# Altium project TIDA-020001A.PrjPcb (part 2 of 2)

## Sheet TIDA-020001A_LM74700&LMR14030.SchDoc
size 457 x 279 mm; Date: Not shown in title block; ApprovedBy: Not shown in title block; CheckedBy: Not shown in title block; Author: Not shown in title block; CompanyName: Not shown in title block; Engineer: Not shown in title block; Organization: Not shown in title block; Address1: Not shown in title block; Address2: Not shown in title block; Address3: Not shown in title block; Address4: Not shown in title block; DocumentNumber: 1; Revision: Use project parameter SCH_Rev; SheetNumber: 2; SheetTotal: 3; PageSetup: Record=PageOptions¦CenterHorizontal=True¦CenterVertical=True¦PrintScale=1.00¦XCorrection=1.00¦YCorrection=1.00¦PrintKind=0¦BorderSize=5000000¦LeftOffset=0¦BottomOffset=0¦Orientation=2¦PaperLength=1000¦PaperWidth=1000¦Scale=100¦PaperSource=15¦PrintQuality=600¦MediaType=1¦DitherType=10¦PaperKind=Letter¦PrintScaleMode=1
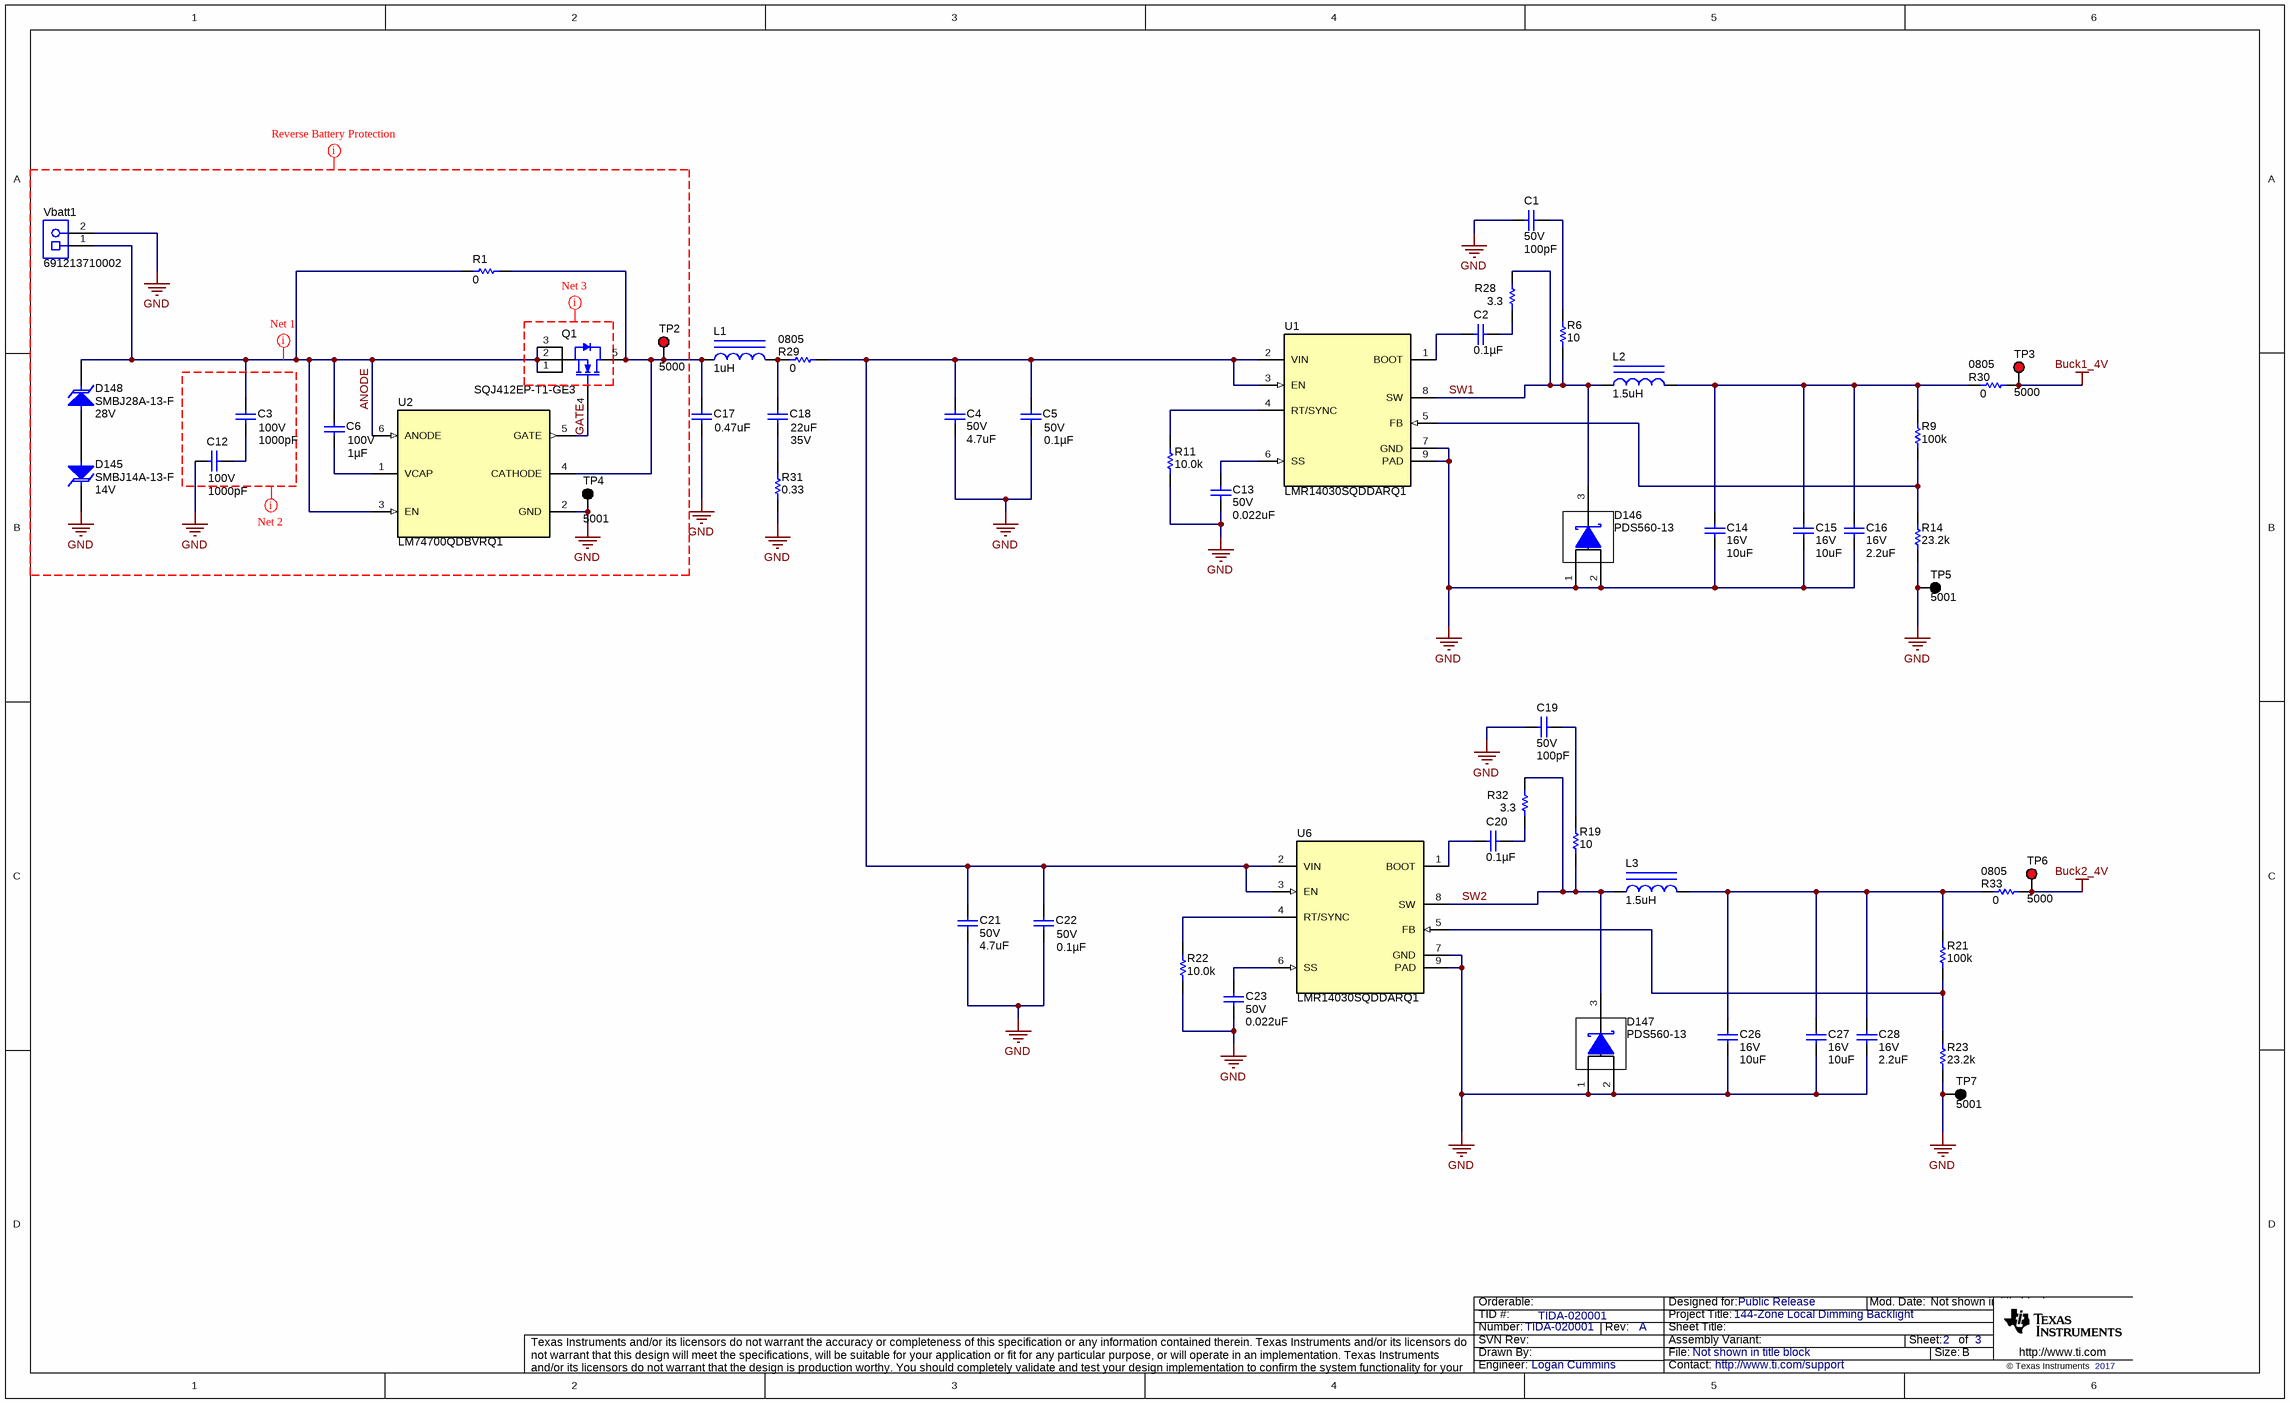
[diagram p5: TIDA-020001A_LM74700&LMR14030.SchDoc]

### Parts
C1  VDC_V: 50V  ValueDisplayed: 100pF  [0402]  (hidden comment: 04025A101FAT2A)
C2  ValueDisplayed: 0.1µF  [0603]  (hidden comment: GRM188R71C104KA01D)
C3  ValueDisplayed: 1000pF  Value2: 100V  [0805_HV]  (hidden comment: 08051A102JAT2A)
C4  VDC_V: 50V  ValueDisplayed: 4.7uF  [1206_180]  (hidden comment: C3216X7R1H475K160AC)
C5  ValueDisplayed: 0.1µF  Value2: 50V  [0805_HV]  (hidden comment: C2012X5R1H104M085AA)
C6  ValueDisplayed: 1µF  Value2: 100V  [1206_180]  (hidden comment: C3216X7R2A105K160AA)
C12  ValueDisplayed: 1000pF  Value2: 100V  [0805_HV]  (hidden comment: 08051A102JAT2A)
C13  VDC_V: 50V  ValueDisplayed: 0.022uF  [0603]  (hidden comment: C0603C223K5RACTU)
C14  VDC_V: 16V  ValueDisplayed: 10uF  [0805_HV]  (hidden comment: CL21B106KOQNNNE)
C15  VDC_V: 16V  ValueDisplayed: 10uF  [0805_HV]  (hidden comment: CL21B106KOQNNNE)
C16  VDC_V: 16V  ValueDisplayed: 2.2uF  [0805_HV]  (hidden comment: C0805C225K4RACTU)
C17  value 0.47uF  [0805_HV]  (hidden comment: C2012X5R1H474K125AB)
C18  ValueDisplayed: 22uF  VDC_V: 35V  [1206_180]  (hidden comment: C3216X5R1V226M160AC)
C19  VDC_V: 50V  ValueDisplayed: 100pF  [0402]  (hidden comment: 04025A101FAT2A)
C20  ValueDisplayed: 0.1µF  [0603]  (hidden comment: GRM188R71C104KA01D)
C21  VDC_V: 50V  ValueDisplayed: 4.7uF  [1206_180]  (hidden comment: C3216X7R1H475K160AC)
C22  ValueDisplayed: 0.1µF  Value2: 50V  [0805_HV]  (hidden comment: C2012X5R1H104M085AA)
C23  VDC_V: 50V  ValueDisplayed: 0.022uF  [0603]  (hidden comment: C0603C223K5RACTU)
C26  VDC_V: 16V  ValueDisplayed: 10uF  [0805_HV]  (hidden comment: CL21B106KOQNNNE)
C27  VDC_V: 16V  ValueDisplayed: 10uF  [0805_HV]  (hidden comment: CL21B106KOQNNNE)
C28  VDC_V: 16V  ValueDisplayed: 2.2uF  [0805_HV]  (hidden comment: C0805C225K4RACTU)
D145  SMBJ14A-13-F  value 14V  [SMB]
D146  PDS560-13  [POWERDI5]
D147  PDS560-13  [POWERDI5]
D148  SMBJ28A-13-F  value 28V  [SMB]
L1  ValueDisplayed: 1uH  [XEL4030_310]  (hidden comment: XEL4030-102MEB)
L2  ValueDisplayed: 1.5uH  [XEL4030_320]  (hidden comment: XEL4030-152MEB)
L3  ValueDisplayed: 1.5uH  [XEL4030_320]  (hidden comment: XEL4030-152MEB)
Q1  SQJ412EP-T1-GE3  [PowerPAK_SO-8L]
R1  ValueDisplayed: 0  [0603]  (hidden comment: CRCW06030000Z0EA)
R6  ValueDisplayed: 10  [0402]  (hidden comment: CRCW040210R0JNED)
R9  ValueDisplayed: 100k  [0603]  (hidden comment: CRCW0603100KFKEA)
R11  ValueDisplayed: 10.0k  [0603]  (hidden comment: CRCW060310K0FKEA)
R14  ValueDisplayed: 23.2k  [0603]  (hidden comment: RC0603FR-0723K2L)
R19  ValueDisplayed: 10  [0402]  (hidden comment: CRCW040210R0JNED)
R21  ValueDisplayed: 100k  [0603]  (hidden comment: CRCW0603100KFKEA)
R22  ValueDisplayed: 10.0k  [0603]  (hidden comment: CRCW060310K0FKEA)
R23  ValueDisplayed: 23.2k  [0603]  (hidden comment: RC0603FR-0723K2L)
R28  ValueDisplayed: 3.3  [0402]  (hidden comment: CRCW04023R30JNED)
R29  PackageReference: 0805  ValueDisplayed: 0  [0805_HV]  (hidden comment: CRCW08050000Z0EA)
R30  PackageReference: 0805  ValueDisplayed: 0  [0805_HV]  (hidden comment: CRCW08050000Z0EA)
R31  ValueDisplayed: 0.33  [0603]  (hidden comment: ERJ-3RQFR33V)
R32  ValueDisplayed: 3.3  [0402]  (hidden comment: CRCW04023R30JNED)
R33  PackageReference: 0805  ValueDisplayed: 0  [0805_HV]  (hidden comment: CRCW08050000Z0EA)
TP2  5000  [Keystone5000]
TP3  5000  [Keystone5000]
TP4  5001  [Keystone5001]
TP5  5001  [Keystone5001]
TP6  5000  [Keystone5000]
TP7  5001  [Keystone5001]
U1  LMR14030SQDDARQ1  [DDA0008E_L]
U2  LM74700QDBVRQ1  [DBV0006A_N]
U6  LMR14030SQDDARQ1  [DDA0008E_L]
Vbatt1  691213710002  [Wurth_691213710002]

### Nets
Buck1_4V: R30.2 TP3.1
Buck2_4V: R33.2 TP6.1
GND: C1.2 C4.2 C5.1 C12.2 C13.2 C14.2 C15.2 C16.2 C17.2 C19.2 C21.2 C22.1 C23.2 C26.2 C27.2 C28.2 D145.1(K) D146.1(A) D146.2(A) D147.1(A) D147.2(A) R11.1 R14.1 R22.1 R23.1 R31.1 TP4.1 TP5.1 TP7.1 U1.7(GND) U1.9(PAD) U2.2(GND) U6.7(GND) U6.9(PAD) Vbatt1.2
ANODE: C3.1 C6.1 D148.1(K) Q1.1(S) Q1.2(S) Q1.3(S) R1.1 U2.3(EN) U2.6(ANODE) Vbatt1.1
GATE: Q1.4(G) U2.5(GATE)
SW1: D146.3(K) L2.1 R6.1 R28.2 U1.8(SW)
SW2: D147.3(K) L3.1 R19.1 R32.2 U6.8(SW)
NetC1_1: C1.1 R6.2
NetC2_1: C2.1 U1.1(BOOT)
NetC2_2: C2.2 R28.1
NetC3_2: C3.2 C12.1
NetC4_1: C4.1 C5.2 C21.1 C22.2 R29.2 U1.2(VIN) U1.3(EN) U6.2(VIN) U6.3(EN)
NetC6_2: C6.2 U2.1(VCAP)
NetC13_1: C13.1 U1.6(SS)
NetC14_1: C14.1 C15.1 C16.1 L2.2 R9.1 R30.1
NetC17_1: C17.1 L1.1 Q1.5(D) R1.2 TP2.1 U2.4(CATHODE)
NetC18_1: C18.1 L1.2 R29.1
NetC18_2: C18.2 R31.2
NetC19_1: C19.1 R19.2
NetC20_1: C20.1 U6.1(BOOT)
NetC20_2: C20.2 R32.1
NetC23_1: C23.1 U6.6(SS)
NetC26_1: C26.1 C27.1 C28.1 L3.2 R21.1 R33.1
NetD145_2: D145.2(A) D148.2(A)
NetR9_2: R9.2 R14.2 U1.5(FB)
NetR11_2: R11.2 U1.4(RT/SYNC)
NetR21_2: R21.2 R23.2 U6.5(FB)
NetR22_2: R22.2 U6.4(RT/SYNC)

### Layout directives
net class Undefined: (no net found under the mark), ANODE, GATE, GND

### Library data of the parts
C1 C19 = CMP-0006196-2: CAP, CERM, 100 pF, 50 V, +/- 1%, C0G/NP0, 0402; Manufacturer: AVX; TaMin_C: -55°C; Polarized: N; SizeAreaWB_mm2: 3; Value1: Unknown; U/M: EA; Value: 100pF; TaMax_C: 125°C; SizeZ_mm: 0.6; SizeX_mm: 1; SizeY_mm: 0.5; CompType: Capacitor; AEC Category: Q200
C2 C20 = GRM188R71C104KA01D: CAP, CERM, 0.1 µF, 16 V, +/- 10%, X7R, 0603; Manufacturer: MuRata; Polarized: N; CompType: Capacitor; Value: 0.1uF; U/M: EA; Cap_F: 0.0000001; Tolerance_%: 10; Value1: Unknown; VDC_V: 16; Value2: 16V; TaMin_C: -55; TaMax_C: 125; SizeArea_mm2: 1.28; SizeAreaWB_mm2: 4.68; SizeX_mm: 1.6; SizeY_mm: 0.8; SizeZ_mm: 1; AEC Category: Q200
C3 C12 = 08051A102JAT2A: CAP, CERM, 1000 pF, 100 V, +/- 5%, C0G/NP0, 0805; Manufacturer: AVX; Polarized: N; CompType: Capacitor; Value: 1000pF; U/M: EA; Cap_F: 0.000000001; Tolerance_%: 5; ESR_ohm: 0.112; Value1: 0.112 ohm; VDC_V: 100; TaMin_C: -55; TaMax_C: 125; Cap_Case: 0805; SizeArea_mm2: 2.5; SizeAreaWB_mm2: 6.75; SizeX_mm: 2; SizeY_mm: 1.25; SizeZ_mm: 1.45; AEC Category: Q200
C4 = CMP-0008702-2: CAP, CERM, 4.7 uF, 50 V, +/- 10%, X7R, 1206; Manufacturer: TDK; Cap_F: 4.7µF; SizeAreaWB_mm2: 10.92; SizeArea_mm2: 5.12; AEC Qualified: N; AEC Category: Q200; Value: 4.7uF; TaMax_C: 125°C; SizeZ_mm: 1.8; TaMin_C: -55°C; SizeY_mm: 1.6; U/M: EA; CompType: Capacitor; SizeX_mm: 3.2; ESR_ohm: 3.158m; IRMS_A: 4.08379A; Value1: 0.003158 ohm
C5 C22 = C2012X5R1H104M085AA: CAP, CERM, 0.1 µF, 50 V,+/- 20%, X5R, 0805; Manufacturer: TDK; Polarized: N; CompType: Capacitor; Value: 0.1uF; U/M: EA; Cap_F: 0.0000001; Tolerance_%: 20; ESR_ohm: 0.02619; Value1: 0.02619 ohm; VDC_V: 50; IRMS_A: 1.29514; TaMin_C: -55; TaMax_C: 85; Cap_Case: 0805; SizeArea_mm2: 2.5; SizeAreaWB_mm2: 6.75; SizeX_mm: 2; SizeY_mm: 1.25; SizeZ_mm: 1.45; AEC Category: Q200; Green_Lifecycle: NRND; Green_REACh: Passed
C6 = C3216X7R2A105K160AA: CAP, CERM, 1 µF, 100 V, +/- 10%, X7R, 1206; Manufacturer: TDK; Polarized: N; CompType: Capacitor; Value: 1uF; U/M: EA; Cap_F: 0.000001; Tolerance_%: 10; ESR_ohm: 0.004575; Value1: 0.004575 ohm; VDC_V: 100; IRMS_A: 3.39639; TaMin_C: -55; TaMax_C: 125; SizeArea_mm2: 5.12; SizeAreaWB_mm2: 10.92; SizeX_mm: 3.2; SizeY_mm: 1.6; SizeZ_mm: 1.8; AEC Category: Q200
C13 C23 = CMP-0006901-4: CAP, CERM, 0.022 uF, 50 V, +/- 10%, X7R, 0603; Manufacturer: Kemet; TaMin_C: -55°C; Polarized: N; Value1: Unknown; U/M: EA; TaMax_C: 125°C; SizeAreaWB_mm2: 4.68; SizeZ_mm: 1; SizeX_mm: 1.6; SizeY_mm: 0.8; SizeArea_mm2: 1.28; CompType: Capacitor; Cap_F: 22nF; AEC Category: Q200
C14 C15 C26 C27 = CMP-0007995-2: CAP, CERM, 10 uF, 16 V, +/- 10%, X7R, 0805; Manufacturer: Samsung Electro-Mechanics; TaMin_C: -55°C; Polarized: N; SizeAreaWB_mm2: 6.75; Value1: Unknown; U/M: EA; Value: 10uF; TaMax_C: 125°C; SizeZ_mm: 1.45; SizeX_mm: 2; SizeY_mm: 1.25; Cap_Case: 0805; SizeArea_mm2: 2.5; Cap_F: 10µF; AEC Category: Q200
C16 C28 = CMP-0007770-2: CAP, CERM, 2.2 uF, 16 V, +/- 10%, X7R, 0805; Manufacturer: Kemet; TaMin_C: -55°C; Polarized: N; SizeAreaWB_mm2: 6.75; Value1: 0.008 ohm; U/M: EA; Value: 2.2uF; TaMax_C: 125°C; SizeZ_mm: 1.45; SizeX_mm: 2; SizeY_mm: 1.25; Cap_Case: 0805; SizeArea_mm2: 2.5; Cap_F: 2.2µF; AEC Category: Q200; ESR_ohm: 8m; IRMS_A: 15.55A
C17 = CMP-0007839-2: CAP, CERM, 0.47 uF, 50 V, +/- 10%, X5R, 0805; Cap_F: 470nF; SizeAreaWB_mm2: 6.75; SizeArea_mm2: 2.5; AEC Qualified: N; AEC Category: Q200; U/M: EA; SizeX_mm: 2
C18 = CMP-0008667-2: CAP, CERM, 22 uF, 35 V, +/- 20%, X5R, 1206; Manufacturer: TDK; TaMin_C: -55°C; Polarized: N; SizeAreaWB_mm2: 10.92; Value1: 0.002398 ohm; U/M: EA; Value: 22uF; TaMax_C: 85°C; SizeZ_mm: 1.8; SizeX_mm: 3.2; SizeY_mm: 1.6; SizeArea_mm2: 5.12; CompType: Capacitor; Cap_F: 22µF; AEC Category: Q200; ESR_ohm: 2.398m; IRMS_A: 4.68507A
C21 = CMP-0008702-2: CAP, CERM, 4.7 uF, 50 V, +/- 10%, X7R, 1206; Manufacturer: TDK; TaMin_C: -55°C; ESR_ohm: 3.158m; Polarized: N; SizeAreaWB_mm2: 10.92; Value1: 0.003158 ohm; U/M: EA; Value: 4.7uF; TaMax_C: 125°C; SizeZ_mm: 1.8; SizeX_mm: 3.2; SizeY_mm: 1.6; SizeArea_mm2: 5.12; CompType: Capacitor; Cap_F: 4.7µF; IRMS_A: 4.08379A; AEC Category: Q200
D145 = SMBJ14A-13-F: Diode, TVS, Uni, 14 V, 600 W, SMB; Manufacturer: Diodes Inc.; U/M: EA; Power_W: 5; Vr_V: 14; Value1: 5W; SizeAreaWB_mm2: 44.156; SizeArea_mm2: 21.336; SizeX_mm: 5.6; SizeY_mm: 3.81; SizeZ_mm: 2.6; AEC Category: Q101
D146 D147 = CMP-0028523-1: Diode, Schottky, 60 V, 5 A, PowerDI5; Manufacturer: Diodes Inc.; Io_A: 5A; Green_Lifecycle: Active; SizeAreaWB_mm2: 49.56; Vr_V: 60V; Green_REACh: Passed; TJmax_C: 150°C; U/M: EA; Value: 60V; SizeZ_mm: 1.05; SizeX_mm: 6.4; SizeY_mm: 3.9; Vf_V: 6.7dV; Value2: 0.67V; SizeArea_mm2: 24.96; AEC Category: Q101
D148 = SMBJ28A-13-F: Diode, TVS, Uni, 28 V, 600 W, SMB; Manufacturer: Diodes Inc.; U/M: EA; Power_W: 5; Vr_V: 28; Value1: 5W; SizeAreaWB_mm2: 44.156; SizeArea_mm2: 21.336; SizeX_mm: 5.6; SizeY_mm: 3.81; SizeZ_mm: 2.6; AEC Category: Q101
L1 = CMP-0061084-1: Inductor, Shielded, Composite, 1 uH, 9 A, 0.0089 ohm, AEC-Q200 Grade 1, SMD; Manufacturer: Coilcraft; Isat: 9A @ 30% inductance drop; Irms: 10.7A @ 40C rise; SizeAreaWB_mm2: 25; DCR_ohm: 8.9m; Value: 1uH; Imax_A: 9A; SizeZ_mm: 3.1; SizeX_mm: 4; SizeArea_mm2: 16; Ind_H: 1µH; AEC Qualified: Y; AEC Grade: 1; AEC Category: Q200
L2 L3 = CMP-0061086-1: Inductor, Shielded, Composite, 1.5 uH, 8.1 A, 0.0151 ohm, AEC-Q200 Grade 1, SMD; Manufacturer: Coilcraft; Isat: 8.5A @ 30% inductance drop; Irms: 8.1A @ 40C rise; SizeAreaWB_mm2: 25; DCR_ohm: 0.0151; Value: 1.5uH; Imax_A: 8.1A; SizeZ_mm: 3.2; SizeX_mm: 4; SizeArea_mm2: 16; Ind_H: 1.5µH; AEC Qualified: Y; AEC Grade: 1; AEC Category: Q200
Q1 = SQJ412EP-T1-GE3: MOSFET, N-CH, 40 V, 32 A, PowerPAK_SO-8L; Manufacturer: Vishay-Siliconix; Alternate Manufacturer: None; SymbolCreator: a0412235; U/M: EA; ChType: N; Value: 40V; VdsMax_V: 40; Value1: 0.0052 ohm; Rdson45_ohm: 0.0052; Value2: 80 nC; QgTyp_nC: 80; Vgs_V: 20; IdsMax_A: 32; AEC Category: Q101
R1 = CRCW06030000Z0EA: RES, 0, 5%, 0.1 W, 0603; Manufacturer: Vishay-Dale; CompType: Resistor; Value: 0; Value_Code: 0000; Tolerance_%: 5; Power_W: 0.1; Value2: 0.1W; VDC_V: 75; TempCo: 200 ppm/C; SizeArea_mm2: 1.28; SizeX_mm: 1.6; SizeY_mm: 0.8; SizeZ_mm: 1; EIA_Code: E24; U/M: EA; AEC Category: Q200; Green_Lifecycle: Active; Green_REACh: Passed
R6 R19 = CMP-0026827-3: RES, 10, 5%, 0.063 W, AEC-Q200 Grade 0, 0402; Manufacturer: Vishay-Dale; Power_W: 63mW; TempCo: 200 ppm/C; Value_Code: 10R0; Value: 10; EIA_Code: E24; SizeX_mm: 1; SizeY_mm: 0.5; SizeZ_mm: 0.6; Value2: 0.063W; CompType: Resistor; AEC Qualified: Y; VDC_V: 50V; AEC Category: Q200; AEC Grade: 0
R9 R21 = CMP-0021990-4: RES, 100 k, 1%, 0.1 W, AEC-Q200 Grade 0, 0603; Manufacturer: Vishay-Dale; Power_W: 100mW; TempCo: 100 ppm/C; Value: 100k; EIA_Code: E96; SizeX_mm: 1.6; SizeY_mm: 0.8; SizeZ_mm: 1; Value2: 0.1W; SizeArea_mm2: 1.28; AEC Qualified: Y; VDC_V: 75V; AEC Category: Q200; AEC Grade: 0
R11 = CMP-0021998-4: RES, 10.0 k, 1%, 0.1 W, AEC-Q200 Grade 0, 0603; Manufacturer: Vishay-Dale; Power_W: 100mW; TempCo: 100 ppm/C; Value_Code: 10k0; Value: 10.0k; EIA_Code: E96; Res_ohm: 10k; SizeX_mm: 1.6; SizeY_mm: 0.8; SizeZ_mm: 1; Value2: 0.1W; SizeArea_mm2: 1.28; CompType: Resistor; AEC Qualified: Y; VDC_V: 75V; AEC Category: Q200; AEC Grade: 0
R14 R23 = CMP-0022933-5: RES, 23.2 k, 1%, 0.1 W, 0603; Manufacturer: Yageo; Power_W: 100mW; TempCo: 100 ppm/C; Value_Code: 23k2; Value: 23.2k; EIA_Code: E96; SizeX_mm: 1.6; SizeY_mm: 0.8; SizeZ_mm: 1; Value2: 0.1W; SizeArea_mm2: 1.28; AEC Qualified: N; VDC_V: 75V; AEC Category: Q200; SizeAreaWB_mm2: 4.68
R22 = CMP-0021998-4: RES, 10.0 k, 1%, 0.1 W, AEC-Q200 Grade 0, 0603; Manufacturer: Vishay-Dale; Power_W: 100mW; TempCo: 100 ppm/C; Value_Code: 10k0; Value: 10.0k; EIA_Code: E96; Res_ohm: 10k; SizeX_mm: 1.6; SizeY_mm: 0.8; SizeZ_mm: 1; Value2: 0.1W; SizeArea_mm2: 1.28; AEC Qualified: Y; VDC_V: 75V; AEC Category: Q200; AEC Grade: 0
R28 R32 = CMP-0026926-3: RES, 3.3, 5%, 0.063 W, AEC-Q200 Grade 0, 0402; Manufacturer: Vishay-Dale; Power_W: 63mW; TempCo: 200 ppm/C; Value_Code: 3R30; Value: 3.3; EIA_Code: E24; SizeX_mm: 1; SizeY_mm: 0.5; SizeZ_mm: 0.6; Value2: 0.063W; CompType: Resistor; AEC Qualified: Y; VDC_V: 50V; AEC Category: Q200; AEC Grade: 0
R29 R30 R33 = CMP-0020442-3: RES, 0, 5%, 0.125 W, AEC-Q200 Grade 0, 0805; Manufacturer: Vishay-Dale; Power_W: 125mW; TempCo: 200 ppm/C; Value_Code: 0000; Value: 0; EIA_Code: E24; SizeX_mm: 2; SizeY_mm: 1.25; SizeZ_mm: 1.45; Value2: 0.125W; SizeArea_mm2: 2.5; CompType: Resistor; AEC Qualified: Y; VDC_V: 150V; AEC Category: Q200
R31 = ERJ-3RQFR33V: RES, 0.33, 1%, 0.1 W, 0603; Manufacturer: Panasonic; CompType: Resistor; Value: 0.33; Value_Code: R330; Tolerance_%: 1; Power_W: 0.1; Value2: 0.1W; TempCo: 300 ppm/C; SizeArea_mm2: 1.28; SizeX_mm: 1.6; SizeY_mm: 0.8; EIA_Code: E96; U/M: EA; AEC Category: Q200; Green_Lifecycle: Active; Green_REACh: Passed
TP2 TP3 TP6 = CMP-0055137-1: Test Point, Miniature, Red, TH; Manufacturer: Keystone; CNHeader: FALSE; Green_Lifecycle: Active; Green_REACh: Passed; ContactFinish: Silver; CT: TRUE
TP4 TP5 TP7 = CMP-0055138-1: Test Point, Miniature, Black, TH; Manufacturer: Keystone; CNHeader: FALSE; Green_Lifecycle: Active; Green_REACh: Passed; ContactFinish: Silver; CT: TRUE
U1 U6 = CMP-0076368-2: Automotive 40V, 3.5A SIMPLE SWITCHER(R), 2.2MHz Step-Down Regulator with 40uA IQ, DDA0008E (SOIC-8); Manufacturer: Texas Instruments; SizeZ_mm: 1.7; SizeX_mm: 5.0; SizeY_mm: 6.2; SizeArea_mm2: 31.0; CompType: IC; U/M: EA; SizeAreaWB_mm2: 57.4
U2 = CMP-0013281-4: Low Iq Always ON Smart Diode Controller, DBV0006A (SOT-23-6); Alternate PartNumber: LM74700QDBVTQ1; Manufacturer: Texas Instruments; SizeZ_mm: 1.45; SizeX_mm: 2.8; SizeY_mm: 2.9; SizeArea_mm2: 8.12; CompType: IC; SizeAreaWB_mm2: 14.82; AEC Category: Q200; AEC Qualified: Y
Vbatt1 = 691213710002: Terminal Block, 2x1, Brass, TH; Manufacturer: Wurth Elektronik; SymbolCreator: a0412235; Pitch_mm: 5; Gender: Female; Row_Count: 1

## Sheet TIDA-020001A_Hardware.SchDoc
size 431 x 279 mm; Date: Not shown in title block; ApprovedBy: Not shown in title block; CheckedBy: Not shown in title block; Author: Not shown in title block; CompanyName: Not shown in title block; Engineer: Not shown in title block; Organization: Not shown in title block; Address1: Not shown in title block; Address2: Not shown in title block; Address3: Not shown in title block; Address4: Not shown in title block; DocumentNumber: 1; Revision: Use project parameter SCH_Rev; SheetNumber: 3; SheetTotal: 3; PageSetup: Record=PageOptions¦CenterHorizontal=True¦CenterVertical=True¦PrintScale=1.00¦XCorrection=1.00¦YCorrection=1.00¦PrintKind=0¦BorderSize=5000000¦LeftOffset=0¦BottomOffset=0¦Orientation=2¦PaperLength=1000¦PaperWidth=1000¦Scale=100¦PaperSource=15¦PrintQuality=600¦MediaType=1¦DitherType=10¦PaperKind=Letter¦PrintScaleMode=1
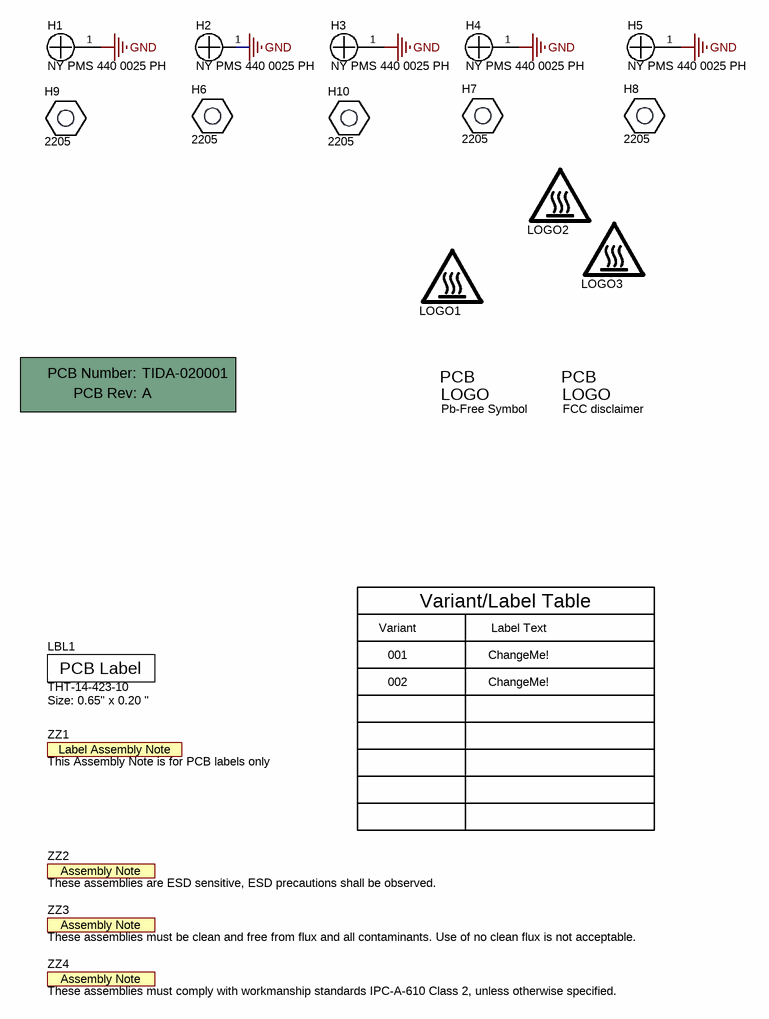
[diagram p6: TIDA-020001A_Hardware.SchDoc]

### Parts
(Parts that share a designator on the sheet are numbered #1, #2 ... from top to bottom, then left to right.)
!PCB  Printed Circuit Board  (value not drawn)  (mechanical)
H1  NY PMS 440 0025 PH  [NY PMS 440 0025 PH]
H2  NY PMS 440 0025 PH  [NY PMS 440 0025 PH]
H3  NY PMS 440 0025 PH  [NY PMS 440 0025 PH]
H4  NY PMS 440 0025 PH  [NY PMS 440 0025 PH]
H5  NY PMS 440 0025 PH  [NY PMS 440 0025 PH]
H6  2205  [KEYSTONE_2205]
H7  2205  [KEYSTONE_2205]
H8  2205  [KEYSTONE_2205]
H9  2205  [KEYSTONE_2205]
H10  2205  [KEYSTONE_2205]
LBL1  THT-14-423-10  Note: Size: 0.65" x 0.20 "  [Label_650x200]
LOGO1  CAUTION HOT SURFACE  [IEC_HotSurface_Small]  (value not drawn)  (no BOM)
LOGO2#1  CAUTION HOT SURFACE  [IEC_HotSurface_Small]  (value not drawn)  (no BOM)
Logo2#2  Pb-Free Symbol  [Pb-Free_Overlay_Small]  (no BOM)
LOGO3#1  CAUTION HOT SURFACE  [IEC_HotSurface_Small]  (value not drawn)  (no BOM)
Logo3#2  FCC disclaimer  [FCC_disclaimer]  (no BOM)
ZZ1  This Assembly Note is for PCB labels only  [AssemblyNoteLabel]  (no BOM)
ZZ2  These assemblies are ESD sensitive, ESD precautions shall be observed.  [AssemblyNote]  (no BOM)
ZZ3  These assemblies must be clean and free from flux and all contaminants. Use of no clean flux is not acceptable.  [AssemblyNote]  (no BOM)
ZZ4  These assemblies must comply with workmanship standards IPC-A-610 Class 2, unless otherwise specified.  [AssemblyNote]  (no BOM)

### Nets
GND: H1.1 H2.1 H3.1 H4.1 H5.1

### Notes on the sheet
- Variant
- Variant/Label Table
- Label Text
- 001
- 002
- ChangeMe!

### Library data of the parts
!PCB = CMP-0003618-2: Manufacturer: Any; PartNumber: TIDA-020001
H1-H5 = NY PMS 440 0025 PH: Machine Screw, Round, #4-40 x 1/4, Nylon, Philips panhead; Manufacturer: B&F Fastener Supply; CompType: Hardware; SymbolCreator: codlsc; U/M: EA
H6-H10 = 2205: Standoff, Hex, 1"L #4-40 Aluminum; Manufacturer: Keystone; SymbolCreator: a0412235
LBL1 = CMP-0003625-1: Thermal Transfer Printable Labels, 0.650" W x 0.200" H - 10,000 per roll; Manufacturer: Brady; CompType: Label
LOGO1 LOGO2#1 LOGO3#1 = IEC_HotSurface: IEC 61010-1 Hot Surface Warning; SymbolCreator: a0412235
Logo2#2 = CMP-0074839-1: SymbolCreator: a0412235; Library Reference: Logo
Logo3#2 = CMP-0074847-1: FCC_disclaimer; Library Reference: Logo
ZZ1 = CMP-0003616-3
ZZ2 = CMP-0077236-1
ZZ3 = CMP-0077237-1
ZZ4 = CMP-0077238-1

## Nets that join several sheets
3V3_LS: TIDA-020001A_TLC6C5724 (14 pins), TIDA-020001A_TLC6C5716 (9 pins), TIDA-020001A_OPT&C2000 (C9.1 R4.2 TP10.1 U4.6)
Buck1_4V: TIDA-020001A_TLC6C5724 (U8.38 U9.38), TIDA-020001A_TLC6C5716 (U14.38), TIDA-020001A_OPT&C2000 (5 pins), TIDA-020001A_LEDs (64 pins), TIDA-020001A_LM74700&LMR14030 (R30.2 TP3.1)
Buck2_4V: TIDA-020001A_TLC6C5724 (U10.38 U11.38), TIDA-020001A_TLC6C5716 (U12.38 U13.38), TIDA-020001A_LEDs (80 pins), TIDA-020001A_LM74700&LMR14030 (R33.2 TP6.1)
GND: TIDA-020001A_TLC6C5724 (24 pins), TIDA-020001A_TLC6C5716 (18 pins), TIDA-020001A_OPT&C2000 (21 pins), TIDA-020001A_LM74700&LMR14030 (35 pins), TIDA-020001A_Hardware (5 pins)
BLANK: TIDA-020001A_TLC6C5724 (U8.36 U9.36 U10.36 U11.36), TIDA-020001A_TLC6C5716 (U12.36 U13.36 U14.36), TIDA-020001A_OPT&C2000 (J1.2)
ERR: TIDA-020001A_TLC6C5724 (6 pins), TIDA-020001A_TLC6C5716 (U12.20 U13.20 U14.20), TIDA-020001A_OPT&C2000 (J2.5)
GCLK: TIDA-020001A_TLC6C5724 (U8.4 U9.4 U10.4 U11.4), TIDA-020001A_TLC6C5716 (U12.4 U13.4 U14.4), TIDA-020001A_OPT&C2000 (R27.1)
LATCH: TIDA-020001A_TLC6C5724 (U8.3 U9.3 U10.3 U11.3), TIDA-020001A_TLC6C5716 (U12.3 U13.3 U14.3), TIDA-020001A_OPT&C2000 (J2.2)
MISO: TIDA-020001A_TLC6C5716 (U14.19), TIDA-020001A_OPT&C2000 (J2.9)
MOSI: TIDA-020001A_TLC6C5724 (U9.1), TIDA-020001A_OPT&C2000 (J1.7)
OUTA0: TIDA-020001A_TLC6C5716 (U12.8), TIDA-020001A_LEDs (D97.1)
OUTA0/1: TIDA-020001A_TLC6C5716 (U13.8), TIDA-020001A_LEDs (D113.1)
OUTA0/3: TIDA-020001A_TLC6C5716 (U14.8), TIDA-020001A_LEDs (D129.1)
OUTA1: TIDA-020001A_TLC6C5716 (R35.2 TP12.1), TIDA-020001A_LEDs (D99.1)
OUTA1/1: TIDA-020001A_TLC6C5716 (U13.11), TIDA-020001A_LEDs (D115.1)
OUTA1/3: TIDA-020001A_TLC6C5716 (U14.11), TIDA-020001A_LEDs (D131.1)
OUTA2: TIDA-020001A_TLC6C5716 (U12.14), TIDA-020001A_LEDs (D101.1)
OUTA2/1: TIDA-020001A_TLC6C5716 (U13.14), TIDA-020001A_LEDs (D117.1)
OUTA2/3: TIDA-020001A_TLC6C5716 (U14.14), TIDA-020001A_LEDs (D133.1)
OUTA3: TIDA-020001A_TLC6C5716 (U12.17), TIDA-020001A_LEDs (D103.1)
OUTA3/1: TIDA-020001A_TLC6C5716 (U13.17), TIDA-020001A_LEDs (D119.1)
OUTA3/3: TIDA-020001A_TLC6C5716 (U14.17), TIDA-020001A_LEDs (D135.1)
OUTA4: TIDA-020001A_TLC6C5716 (U12.22), TIDA-020001A_LEDs (D105.1)
OUTA4/1: TIDA-020001A_TLC6C5716 (U13.22), TIDA-020001A_LEDs (D121.1)
OUTA4/3: TIDA-020001A_TLC6C5716 (U14.22), TIDA-020001A_LEDs (D137.1)
OUTA5: TIDA-020001A_TLC6C5716 (U12.25), TIDA-020001A_LEDs (D107.1)
OUTA5/1: TIDA-020001A_TLC6C5716 (U13.25), TIDA-020001A_LEDs (D123.1)
OUTA5/3: TIDA-020001A_TLC6C5716 (U14.25), TIDA-020001A_LEDs (D139.1)
OUTA6: TIDA-020001A_TLC6C5716 (U12.28), TIDA-020001A_LEDs (D109.1)
OUTA6/1: TIDA-020001A_TLC6C5716 (U13.28), TIDA-020001A_LEDs (D125.1)
OUTA6/3: TIDA-020001A_TLC6C5716 (U14.28), TIDA-020001A_LEDs (D141.1)
OUTA7: TIDA-020001A_TLC6C5716 (U12.31), TIDA-020001A_LEDs (D111.1)
OUTA7/1: TIDA-020001A_TLC6C5716 (U13.31), TIDA-020001A_LEDs (D127.1)
OUTA7/3: TIDA-020001A_TLC6C5716 (U14.31), TIDA-020001A_LEDs (D143.1)
OUTB0: TIDA-020001A_TLC6C5724 (U8.9), TIDA-020001A_LEDs (D3.1)
OUTB0/1: TIDA-020001A_TLC6C5724 (U9.9), TIDA-020001A_LEDs (D27.1)
OUTB0/2: TIDA-020001A_TLC6C5724 (U10.9), TIDA-020001A_LEDs (D51.1)
OUTB0/3: TIDA-020001A_TLC6C5724 (U11.9), TIDA-020001A_LEDs (D75.1)
OUTB0/4: TIDA-020001A_TLC6C5716 (R34.2 TP1.1), TIDA-020001A_LEDs (D98.1)
OUTB0/5: TIDA-020001A_TLC6C5716 (U13.9), TIDA-020001A_LEDs (D114.1)
OUTB0/7: TIDA-020001A_TLC6C5716 (U14.9), TIDA-020001A_LEDs (D130.1)
OUTB1: TIDA-020001A_TLC6C5724 (U8.12), TIDA-020001A_LEDs (D6.1)
OUTB1/1: TIDA-020001A_TLC6C5724 (U9.12), TIDA-020001A_LEDs (D30.1)
OUTB1/2: TIDA-020001A_TLC6C5724 (U10.12), TIDA-020001A_LEDs (D54.1)
OUTB1/3: TIDA-020001A_TLC6C5724 (U11.12), TIDA-020001A_LEDs (D78.1)
OUTB1/4: TIDA-020001A_TLC6C5716 (U12.12), TIDA-020001A_LEDs (D100.1)
OUTB1/5: TIDA-020001A_TLC6C5716 (U13.12), TIDA-020001A_LEDs (D116.1)
OUTB1/7: TIDA-020001A_TLC6C5716 (U14.12), TIDA-020001A_LEDs (D132.1)
OUTB2: TIDA-020001A_TLC6C5724 (U8.15), TIDA-020001A_LEDs (D9.1)
OUTB2/1: TIDA-020001A_TLC6C5724 (U9.15), TIDA-020001A_LEDs (D33.1)
OUTB2/2: TIDA-020001A_TLC6C5724 (U10.15), TIDA-020001A_LEDs (D57.1)
OUTB2/3: TIDA-020001A_TLC6C5724 (U11.15), TIDA-020001A_LEDs (D81.1)
OUTB2/4: TIDA-020001A_TLC6C5716 (U12.15), TIDA-020001A_LEDs (D102.1)
OUTB2/5: TIDA-020001A_TLC6C5716 (U13.15), TIDA-020001A_LEDs (D118.1)
OUTB2/7: TIDA-020001A_TLC6C5716 (U14.15), TIDA-020001A_LEDs (D134.1)
OUTB3: TIDA-020001A_TLC6C5724 (U8.18), TIDA-020001A_LEDs (D12.1)
OUTB3/1: TIDA-020001A_TLC6C5724 (U9.18), TIDA-020001A_LEDs (D36.1)
OUTB3/2: TIDA-020001A_TLC6C5724 (U10.18), TIDA-020001A_LEDs (D60.1)
OUTB3/3: TIDA-020001A_TLC6C5724 (U11.18), TIDA-020001A_LEDs (D84.1)
OUTB3/4: TIDA-020001A_TLC6C5716 (U12.18), TIDA-020001A_LEDs (D104.1)
OUTB3/5: TIDA-020001A_TLC6C5716 (U13.18), TIDA-020001A_LEDs (D120.1)
OUTB3/7: TIDA-020001A_TLC6C5716 (U14.18), TIDA-020001A_LEDs (D136.1)
OUTB4: TIDA-020001A_TLC6C5724 (U8.21), TIDA-020001A_LEDs (D15.1)
OUTB4/1: TIDA-020001A_TLC6C5724 (U9.21), TIDA-020001A_LEDs (D39.1)
OUTB4/2: TIDA-020001A_TLC6C5724 (U10.21), TIDA-020001A_LEDs (D63.1)
OUTB4/3: TIDA-020001A_TLC6C5724 (U11.21), TIDA-020001A_LEDs (D87.1)
OUTB4/4: TIDA-020001A_TLC6C5716 (U12.21), TIDA-020001A_LEDs (D106.1)
OUTB4/5: TIDA-020001A_TLC6C5716 (U13.21), TIDA-020001A_LEDs (D122.1)
OUTB4/7: TIDA-020001A_TLC6C5716 (U14.21), TIDA-020001A_LEDs (D138.1)
OUTB5: TIDA-020001A_TLC6C5724 (U8.24), TIDA-020001A_LEDs (D18.1)
OUTB5/1: TIDA-020001A_TLC6C5724 (U9.24), TIDA-020001A_LEDs (D42.1)
OUTB5/2: TIDA-020001A_TLC6C5724 (U10.24), TIDA-020001A_LEDs (D66.1)
OUTB5/3: TIDA-020001A_TLC6C5724 (U11.24), TIDA-020001A_LEDs (D90.1)
OUTB5/4: TIDA-020001A_TLC6C5716 (U12.24), TIDA-020001A_LEDs (D108.1)
OUTB5/5: TIDA-020001A_TLC6C5716 (U13.24), TIDA-020001A_LEDs (D124.1)
OUTB5/7: TIDA-020001A_TLC6C5716 (U14.24), TIDA-020001A_LEDs (D140.1)
OUTB6: TIDA-020001A_TLC6C5724 (U8.27), TIDA-020001A_LEDs (D21.1)
OUTB6/1: TIDA-020001A_TLC6C5724 (U9.27), TIDA-020001A_LEDs (D45.1)
OUTB6/2: TIDA-020001A_TLC6C5724 (U10.27), TIDA-020001A_LEDs (D69.1)
OUTB6/3: TIDA-020001A_TLC6C5724 (U11.27), TIDA-020001A_LEDs (D93.1)
OUTB6/4: TIDA-020001A_TLC6C5716 (U12.27), TIDA-020001A_LEDs (D110.1)
OUTB6/5: TIDA-020001A_TLC6C5716 (U13.27), TIDA-020001A_LEDs (D126.1)
OUTB6/7: TIDA-020001A_TLC6C5716 (U14.27), TIDA-020001A_LEDs (D142.1)
OUTB7: TIDA-020001A_TLC6C5724 (U8.30), TIDA-020001A_LEDs (D24.1)
OUTB7/1: TIDA-020001A_TLC6C5724 (U9.30), TIDA-020001A_LEDs (D48.1)
OUTB7/2: TIDA-020001A_TLC6C5724 (U10.30), TIDA-020001A_LEDs (D72.1)
OUTB7/3: TIDA-020001A_TLC6C5724 (U11.30), TIDA-020001A_LEDs (D96.1)
OUTB7/4: TIDA-020001A_TLC6C5716 (U12.30), TIDA-020001A_LEDs (D112.1)
OUTB7/5: TIDA-020001A_TLC6C5716 (U13.30), TIDA-020001A_LEDs (D128.1)
OUTB7/7: TIDA-020001A_TLC6C5716 (U14.30), TIDA-020001A_LEDs (D144.1)
OUTG0: TIDA-020001A_TLC6C5724 (U8.7), TIDA-020001A_LEDs (D1.1)
OUTG0/1: TIDA-020001A_TLC6C5724 (U9.7), TIDA-020001A_LEDs (D25.1)
OUTG0/2: TIDA-020001A_TLC6C5724 (U10.7), TIDA-020001A_LEDs (D49.1)
OUTG0/3: TIDA-020001A_TLC6C5724 (U11.7), TIDA-020001A_LEDs (D73.1)
OUTG1: TIDA-020001A_TLC6C5724 (U8.10), TIDA-020001A_LEDs (D4.1)
OUTG1/1: TIDA-020001A_TLC6C5724 (U9.10), TIDA-020001A_LEDs (D28.1)
OUTG1/2: TIDA-020001A_TLC6C5724 (U10.10), TIDA-020001A_LEDs (D52.1)
OUTG1/3: TIDA-020001A_TLC6C5724 (U11.10), TIDA-020001A_LEDs (D76.1)
OUTG2: TIDA-020001A_TLC6C5724 (U8.13), TIDA-020001A_LEDs (D7.1)
OUTG2/1: TIDA-020001A_TLC6C5724 (U9.13), TIDA-020001A_LEDs (D31.1)
OUTG2/2: TIDA-020001A_TLC6C5724 (U10.13), TIDA-020001A_LEDs (D55.1)
OUTG2/3: TIDA-020001A_TLC6C5724 (U11.13), TIDA-020001A_LEDs (D79.1)
OUTG3: TIDA-020001A_TLC6C5724 (U8.16), TIDA-020001A_LEDs (D10.1)
OUTG3/1: TIDA-020001A_TLC6C5724 (U9.16), TIDA-020001A_LEDs (D34.1)
OUTG3/2: TIDA-020001A_TLC6C5724 (U10.16), TIDA-020001A_LEDs (D58.1)
OUTG3/3: TIDA-020001A_TLC6C5724 (U11.16), TIDA-020001A_LEDs (D82.1)
OUTG4: TIDA-020001A_TLC6C5724 (U8.23), TIDA-020001A_LEDs (D13.1)
OUTG4/1: TIDA-020001A_TLC6C5724 (U9.23), TIDA-020001A_LEDs (D37.1)
OUTG4/2: TIDA-020001A_TLC6C5724 (U10.23), TIDA-020001A_LEDs (D61.1)
OUTG4/3: TIDA-020001A_TLC6C5724 (U11.23), TIDA-020001A_LEDs (D85.1)
OUTG5: TIDA-020001A_TLC6C5724 (U8.26), TIDA-020001A_LEDs (D16.1)
OUTG5/1: TIDA-020001A_TLC6C5724 (U9.26), TIDA-020001A_LEDs (D40.1)
OUTG5/2: TIDA-020001A_TLC6C5724 (U10.26), TIDA-020001A_LEDs (D64.1)
OUTG5/3: TIDA-020001A_TLC6C5724 (U11.26), TIDA-020001A_LEDs (D88.1)
OUTG6: TIDA-020001A_TLC6C5724 (U8.29), TIDA-020001A_LEDs (D19.1)
OUTG6/1: TIDA-020001A_TLC6C5724 (U9.29), TIDA-020001A_LEDs (D43.1)
OUTG6/2: TIDA-020001A_TLC6C5724 (U10.29), TIDA-020001A_LEDs (D67.1)
OUTG6/3: TIDA-020001A_TLC6C5724 (U11.29), TIDA-020001A_LEDs (D91.1)
OUTG7: TIDA-020001A_TLC6C5724 (U8.32), TIDA-020001A_LEDs (D22.1)
OUTG7/1: TIDA-020001A_TLC6C5724 (U9.32), TIDA-020001A_LEDs (D46.1)
OUTG7/2: TIDA-020001A_TLC6C5724 (U10.32), TIDA-020001A_LEDs (D70.1)
OUTG7/3: TIDA-020001A_TLC6C5724 (U11.32), TIDA-020001A_LEDs (D94.1)
OUTR0: TIDA-020001A_TLC6C5724 (U8.8), TIDA-020001A_LEDs (D2.1)
OUTR0/1: TIDA-020001A_TLC6C5724 (U9.8), TIDA-020001A_LEDs (D26.1)
OUTR0/2: TIDA-020001A_TLC6C5724 (U10.8), TIDA-020001A_LEDs (D50.1)
OUTR0/3: TIDA-020001A_TLC6C5724 (U11.8), TIDA-020001A_LEDs (D74.1)
OUTR1: TIDA-020001A_TLC6C5724 (U8.11), TIDA-020001A_LEDs (D5.1)
OUTR1/1: TIDA-020001A_TLC6C5724 (U9.11), TIDA-020001A_LEDs (D29.1)
OUTR1/2: TIDA-020001A_TLC6C5724 (U10.11), TIDA-020001A_LEDs (D53.1)
OUTR1/3: TIDA-020001A_TLC6C5724 (U11.11), TIDA-020001A_LEDs (D77.1)
OUTR2: TIDA-020001A_TLC6C5724 (U8.14), TIDA-020001A_LEDs (D8.1)
OUTR2/1: TIDA-020001A_TLC6C5724 (U9.14), TIDA-020001A_LEDs (D32.1)
OUTR2/2: TIDA-020001A_TLC6C5724 (U10.14), TIDA-020001A_LEDs (D56.1)
OUTR2/3: TIDA-020001A_TLC6C5724 (U11.14), TIDA-020001A_LEDs (D80.1)
OUTR3: TIDA-020001A_TLC6C5724 (U8.17), TIDA-020001A_LEDs (D11.1)
OUTR3/1: TIDA-020001A_TLC6C5724 (U9.17), TIDA-020001A_LEDs (D35.1)
OUTR3/2: TIDA-020001A_TLC6C5724 (U10.17), TIDA-020001A_LEDs (D59.1)
OUTR3/3: TIDA-020001A_TLC6C5724 (U11.17), TIDA-020001A_LEDs (D83.1)
OUTR4: TIDA-020001A_TLC6C5724 (U8.22), TIDA-020001A_LEDs (D14.1)
OUTR4/1: TIDA-020001A_TLC6C5724 (U9.22), TIDA-020001A_LEDs (D38.1)
OUTR4/2: TIDA-020001A_TLC6C5724 (U10.22), TIDA-020001A_LEDs (D62.1)
OUTR4/3: TIDA-020001A_TLC6C5724 (U11.22), TIDA-020001A_LEDs (D86.1)
OUTR5: TIDA-020001A_TLC6C5724 (U8.25), TIDA-020001A_LEDs (D17.1)
OUTR5/1: TIDA-020001A_TLC6C5724 (U9.25), TIDA-020001A_LEDs (D41.1)
OUTR5/2: TIDA-020001A_TLC6C5724 (U10.25), TIDA-020001A_LEDs (D65.1)
OUTR5/3: TIDA-020001A_TLC6C5724 (U11.25), TIDA-020001A_LEDs (D89.1)
OUTR6: TIDA-020001A_TLC6C5724 (U8.28), TIDA-020001A_LEDs (D20.1)
OUTR6/1: TIDA-020001A_TLC6C5724 (U9.28), TIDA-020001A_LEDs (D44.1)
OUTR6/2: TIDA-020001A_TLC6C5724 (U10.28), TIDA-020001A_LEDs (D68.1)
OUTR6/3: TIDA-020001A_TLC6C5724 (U11.28), TIDA-020001A_LEDs (D92.1)
OUTR7: TIDA-020001A_TLC6C5724 (U8.31), TIDA-020001A_LEDs (D23.1)
OUTR7/1: TIDA-020001A_TLC6C5724 (U9.31), TIDA-020001A_LEDs (D47.1)
OUTR7/2: TIDA-020001A_TLC6C5724 (U10.31), TIDA-020001A_LEDs (D71.1)
OUTR7/3: TIDA-020001A_TLC6C5724 (U11.31), TIDA-020001A_LEDs (D95.1)
SCK: TIDA-020001A_TLC6C5724 (U8.2 U9.2 U10.2 U11.2), TIDA-020001A_TLC6C5716 (U12.2 U13.2 U14.2), TIDA-020001A_OPT&C2000 (R26.1)
SDO8/SDI14: TIDA-020001A_TLC6C5724 (U8.19), TIDA-020001A_TLC6C5716 (U14.1)
SDO10/SDI12: TIDA-020001A_TLC6C5724 (U10.19), TIDA-020001A_TLC6C5716 (U12.1)
SDO13/SDI11: TIDA-020001A_TLC6C5724 (U11.1), TIDA-020001A_TLC6C5716 (U13.19)

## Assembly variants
001: not fitted FID1 FID2 FID3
